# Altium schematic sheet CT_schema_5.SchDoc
size 297 x 271 mm
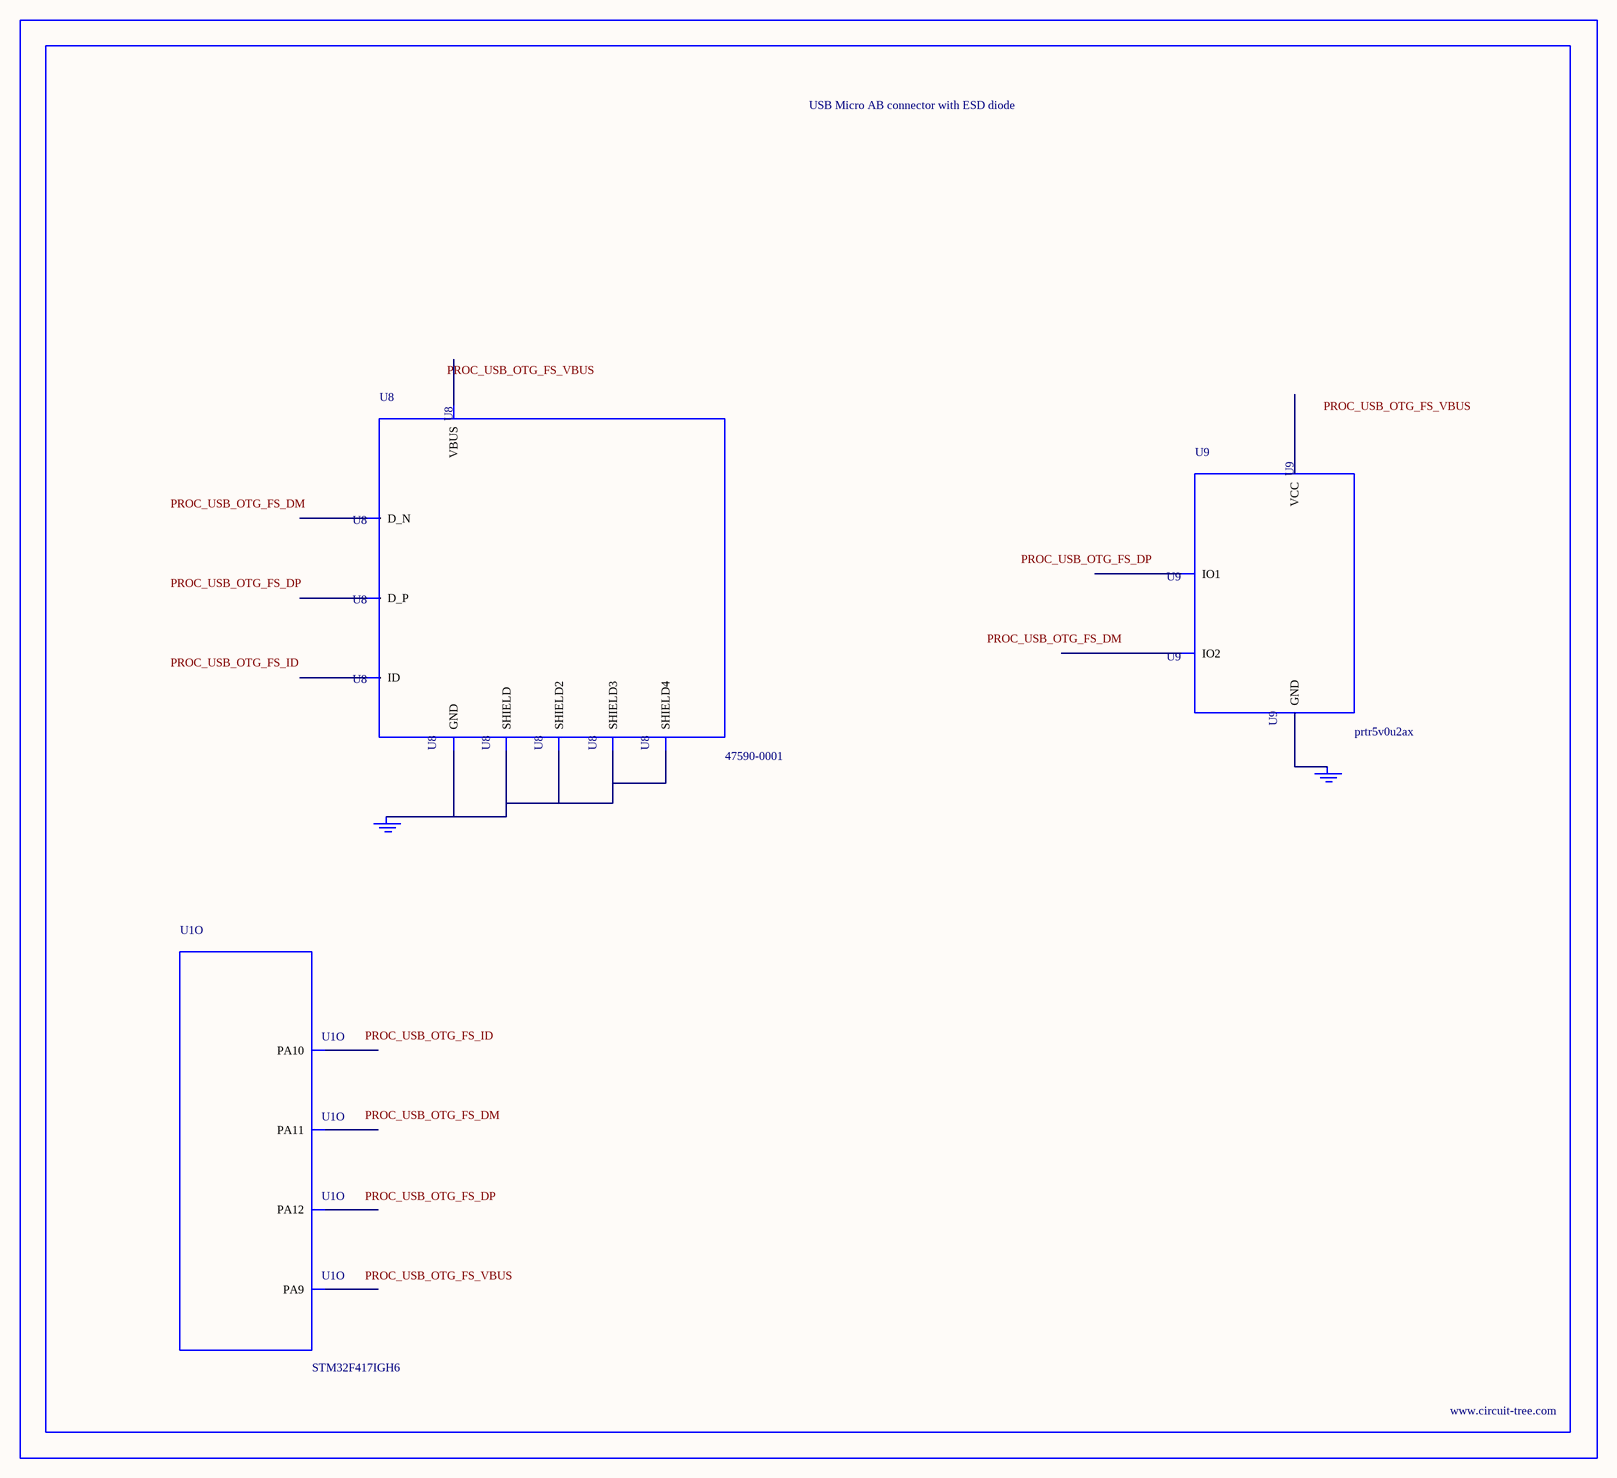
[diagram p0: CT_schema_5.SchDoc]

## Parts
BORDER4  (no value)
GND_INSTANCE_4_0  (no value)
GND_INSTANCE_4_1  (no value)
U1  STM32F417IGH6  [UFBGA176_25]  (part O of 15)
U8  47590-0001  [MICRO_USB_AB]
U9  prtr5v0u2ax  [SOT143B]

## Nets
NetGND_INSTANCE_4_0_0: GND_INSTANCE_4_0.0(GND) U8.5(GND) U8.6(SHIELD) U8.7(SHIELD2) U8.8(SHIELD3) U8.9(SHIELD4)
NetGND_INSTANCE_4_1_0: GND_INSTANCE_4_1.0(GND) U9.1(GND)

Not connected (* = marked no-connect by the designer): U1 B15(PA12) C15(PA11) D15(PA10) E15(PA9); U8 1(VBUS) 2(D_N) 3(D_P) 4(ID); U9 2(IO1) 3(IO2) 4(VCC)

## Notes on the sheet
- Labels drawn without touching a wire or pin: PROC_USB_OTG_FS_DM, PROC_USB_OTG_FS_DP, PROC_USB_OTG_FS_ID, PROC_USB_OTG_FS_VBUS

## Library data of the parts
BORDER4 = BORDER_PAGE4
GND_INSTANCE_4_0 GND_INSTANCE_4_1 = GND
